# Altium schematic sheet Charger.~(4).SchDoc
size A3; SheetNumber: 2; SheetTotal: 2
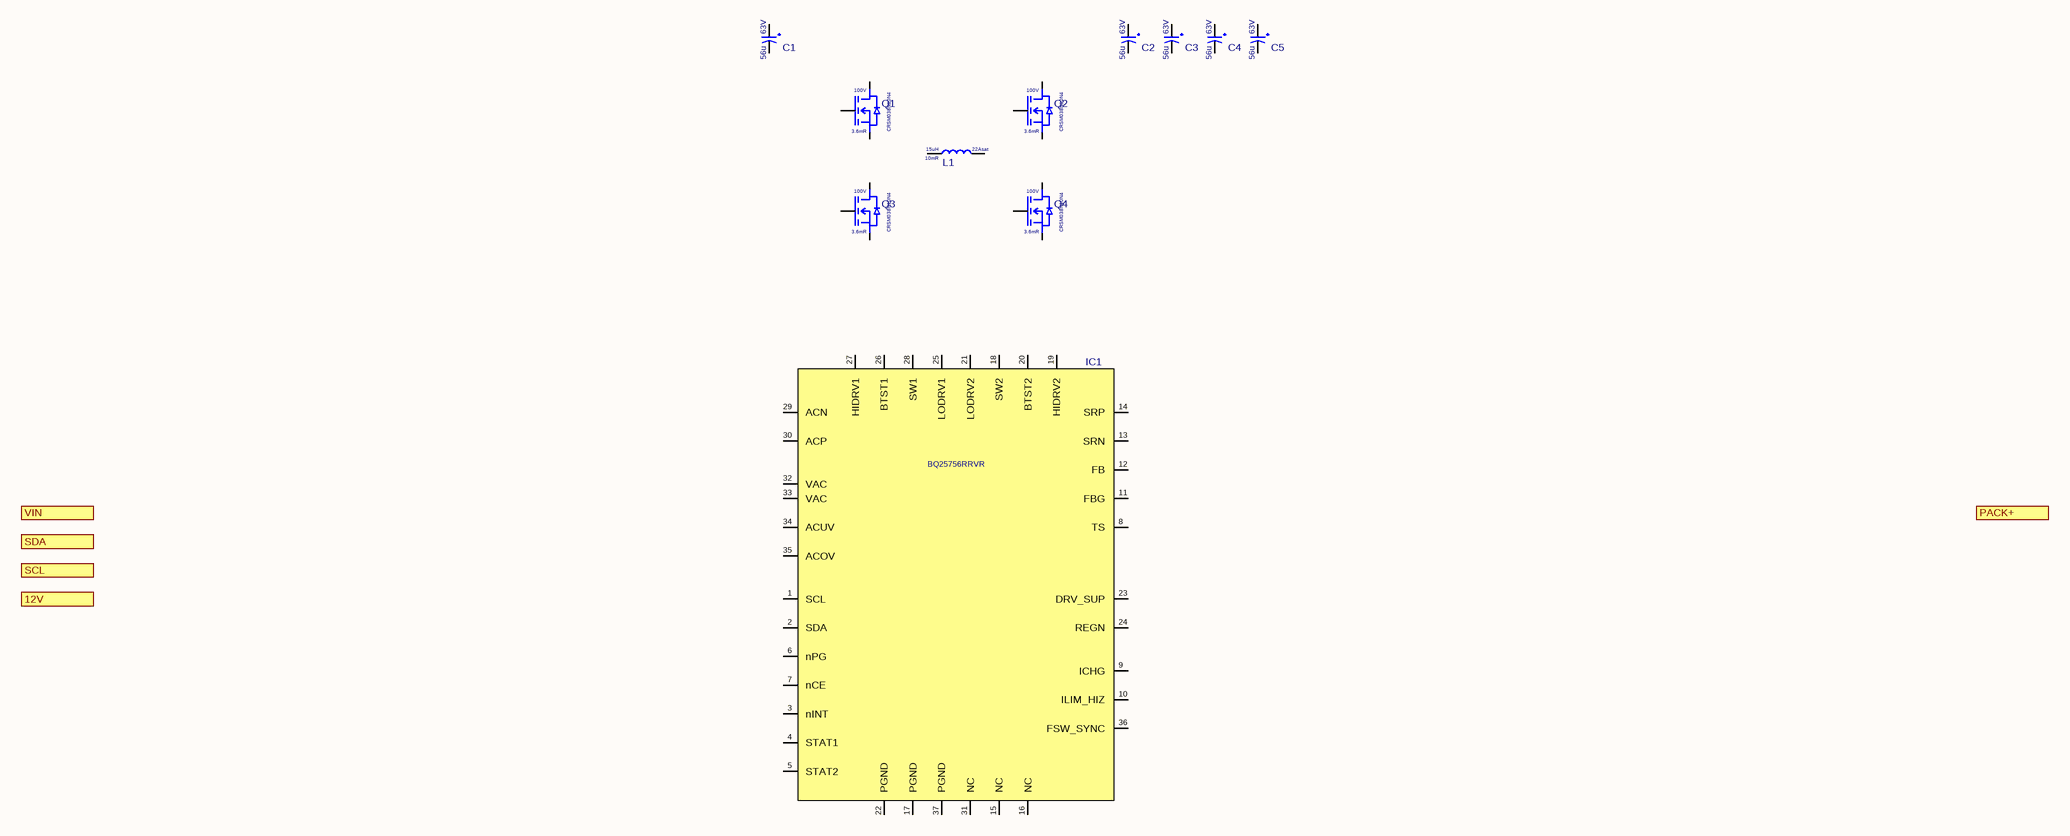
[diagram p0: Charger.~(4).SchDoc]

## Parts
C1  Voltage Rating: 63V  Capacitance: 56u  [CAP_SMD_10X10.2]  (hidden comment: EEHZA1J560P)
C2  Voltage Rating: 63V  Capacitance: 56u  [CAP_SMD_10X10.2]  (hidden comment: EEHZA1J560P)
C3  Voltage Rating: 63V  Capacitance: 56u  [CAP_SMD_10X10.2]  (hidden comment: EEHZA1J560P)
C4  Voltage Rating: 63V  Capacitance: 56u  [CAP_SMD_10X10.2]  (hidden comment: EEHZA1J560P)
C5  Voltage Rating: 63V  Capacitance: 56u  [CAP_SMD_10X10.2]  (hidden comment: EEHZA1J560P)
IC1  BQ25756RRVR  [VQFN-36(5x6)]
L1  Resistance: 10mR  Saturation current: 22Asat  Inductance: 15uH  [MTF1810-150M]  (hidden comment: MTF1810-150M)
Q1  Rds: 3.6mR  Voltage: 100V  [DFN-8 (5x6)]  (hidden comment: CRSM038N10N4)
Q2  Rds: 3.6mR  Voltage: 100V  [DFN-8 (5x6)]  (hidden comment: CRSM038N10N4)
Q3  Rds: 3.6mR  Voltage: 100V  [DFN-8 (5x6)]  (hidden comment: CRSM038N10N4)
Q4  Rds: 3.6mR  Voltage: 100V  [DFN-8 (5x6)]  (hidden comment: CRSM038N10N4)

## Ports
12V (see Arhitecture[5B]), PACK+ (see Arhitecture[6B]), SCL (see Arhitecture[5B]), SDA (see Arhitecture[5B]), VIN (see Arhitecture[5B])

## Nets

Not connected (* = marked no-connect by the designer): C1 + -; C2 + -; C3 + -; C4 + -; C5 + -; IC1 1(SCL) 2(SDA) 3(nINT) 4(STAT1) 5(STAT2) 6(nPG) 7(nCE) 8(TS) 9(ICHG) 10(ILIM_HIZ) 11(FBG) 12(FB) 13(SRN) 14(SRP) 15(NC) 16(NC) 17(PGND) 18(SW2) 19(HIDRV2) 20(BTST2) 21(LODRV2) 22(PGND) 23(DRV_SUP) 24(REGN) 25(LODRV1) 26(BTST1) 27(HIDRV1) 28(SW1) 29(ACN) 30(ACP) 31(NC) 32(VAC) 33(VAC) 34(ACUV) 35(ACOV) 36(FSW_SYNC) 37(PGND); L1 1 2; Q1 D G S; Q2 D G S; Q3 D G S; Q4 D G S

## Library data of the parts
C1-C5 = EEHZA1J560P: Cap AL-EL 56uF 63V 30mR 1.8Ar SMD 10x10.2mm; Manufacturer: Panasonic
IC1 = BQ25756RRVR: Charger IC; Manufacturer: Texas Instruments
L1 = MTF1810-150M: Inductor 15uH 22Asat 10mR SMD 18x18x9 mm; Manufacturer: COILMX
Q1-Q4 = CRSM038N10N4: Nmos 100V 100A 3.6mR DFN-8(5x6); Manufacturer: CRMICRO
